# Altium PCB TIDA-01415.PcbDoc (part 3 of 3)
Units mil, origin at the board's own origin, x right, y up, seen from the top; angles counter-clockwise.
Board outline 3820.95 x 4648 mil, 4 copper layers (Top Layer, GND, PWR, Bottom Layer), stack 5.6 mil thick; 255 components, 113 nets, 599 pads, 415 vias.
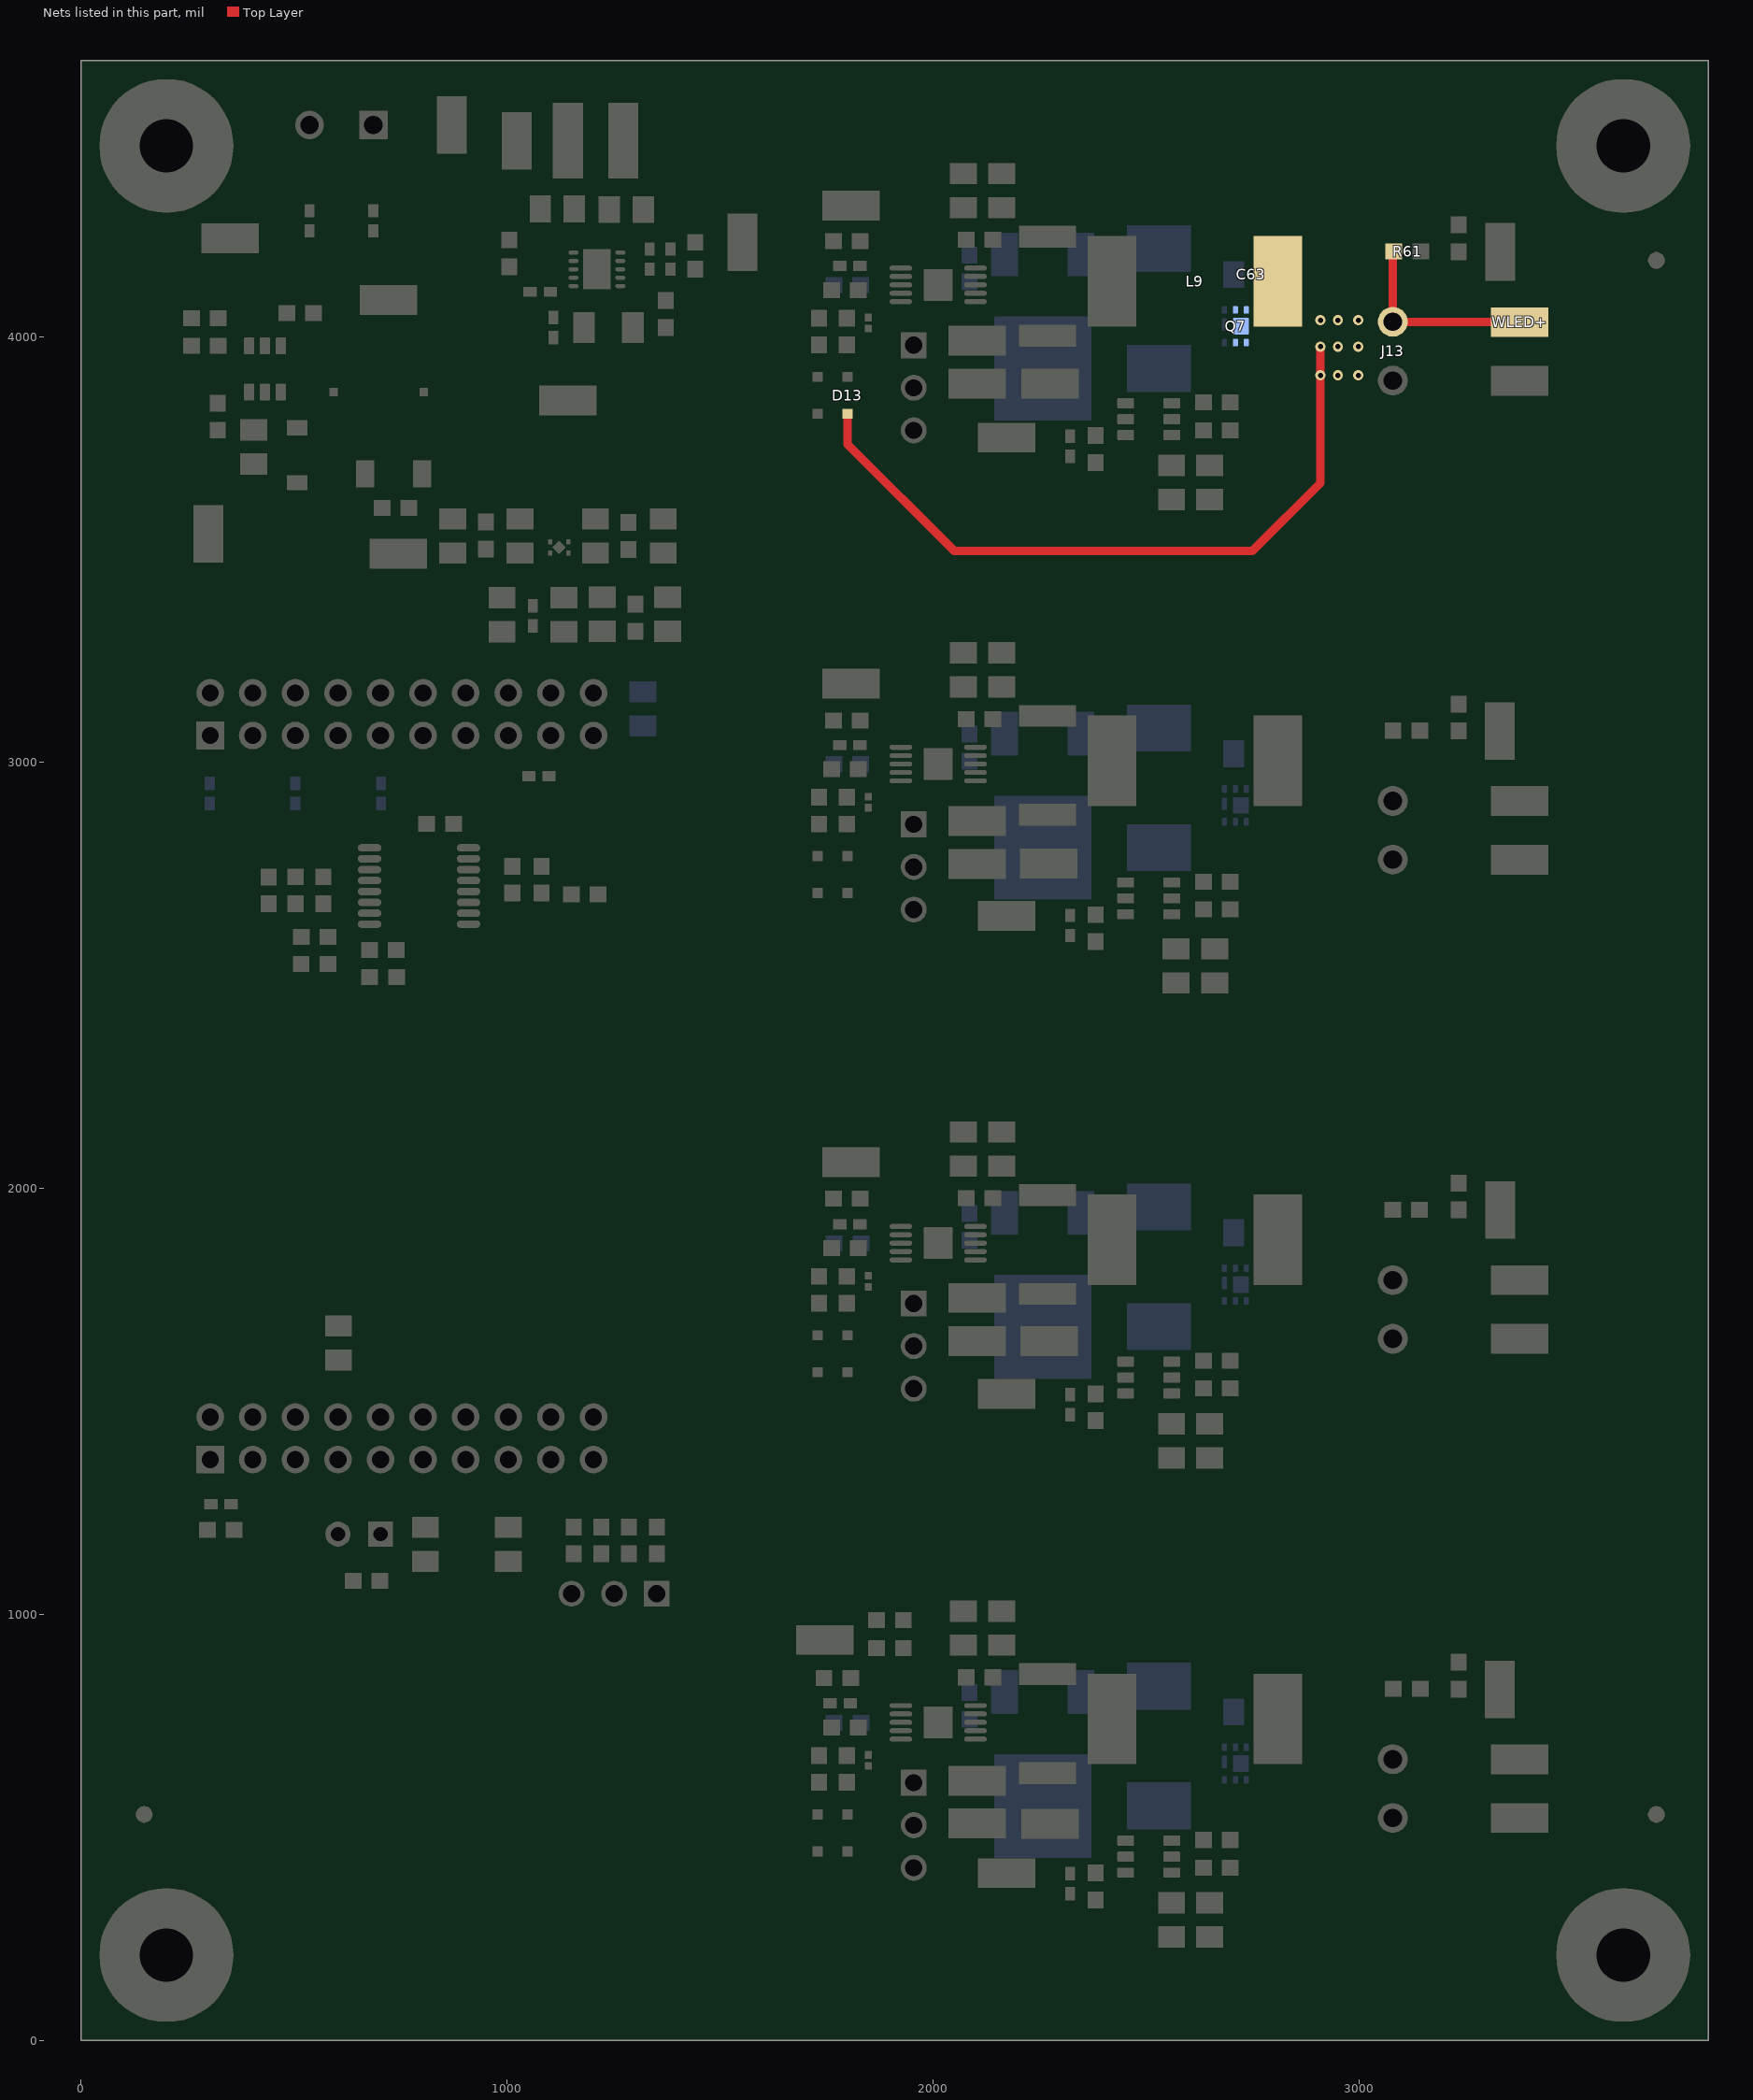
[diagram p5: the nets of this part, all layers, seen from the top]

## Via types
v1: diameter 24, hole 12, Top Layer to Bottom Layer, tented both sides, 213 vias
v2: diameter 20, hole 10, Top Layer to Bottom Layer, tented both sides, 182 vias
v3: diameter 19.68, hole 7.87, Top Layer to Bottom Layer, 20 vias

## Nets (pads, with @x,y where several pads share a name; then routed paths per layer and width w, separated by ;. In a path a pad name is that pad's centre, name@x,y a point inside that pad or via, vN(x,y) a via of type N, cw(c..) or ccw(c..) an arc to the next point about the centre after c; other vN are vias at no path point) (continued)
WLED+: C63.1 D13.2 J13.1 L9.2 Q7.1 Q7.2 Q7.5 Q7.6 Q7.8 R61.2 WLED+.1 | length 2131.3
  Top Layer w20: D13.2@1799.43,3818.69 1799.43,3747.57 2050.1,3496.9 2750,3496.9 2910,3656.9 v1(2910,3909) v1(2910,3976.53) ; R61.2@3080,4197.5 J13.1@3080,4034.8 WLED+.1@3377.2,4034.8
  other v1: 2951,3909 2999,3909 2951,3976.53 2999,3976.53 2910,4038.53 2951,4038.53 2999,4038.53
pads on no net: FID1.1 FID2.1 FID3.1 FID4.1 FID5.1 FID6.1 H1.1 H2.1 H3.1 H4.1 J5.2 J5.3 J5.5 J5.6 J5.7 J5.11 J5.12 J5.14 J5.16 J5.17 J5.19 J5.20 J10.8 J10.10 J10.13 J10.15 J10.17 J10.18 J10.19 Q1.0 Q3.0 Q5.0 Q7.0 U9.6

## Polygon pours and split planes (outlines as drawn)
GND on Top Layer "Top Layer-No Net" (solid, pour order 311): 1100,3336.92 1100,3249 1107,3242 1121,3228 1180.91,3228 1241.51,3228 1257,3243.49 1257,3336 1247,3346 1109.08,3346
GND on Top Layer "Top Layer-No Net" (solid, pour order 310): 1336,3523 1455,3523 1463,3515 1469,3509 1469,3420 1469,3387 1445,3363 1442,3360 1406,3360 1348,3360 1340,3368 1334,3374 1334,3452 1334,3520 1337,3523
+3.6V on Top Layer "Top Layer-No Net" (solid, pour order 305): 19 vertices, not listed, extent 727.5,3540 999,4040.42
+3.3V_D on Top Layer "Top Layer-No Net" (solid, pour order 309): 1276.15,3329.1 1330.46,3328.99 1340,3338.53 1343.47,3342 1366.5,3342 1428,3342 1437,3333 1437,3254 1424,3241 1392,3241 1282,3241 1272.96,3250.04 1272.96,3277.68 1272.96,3325.91
GND on Top Layer "Top Layer-No Net" (solid, pour order 308): 21 vertices, not listed, extent 840,3356.08 1020.31,3523.9
+3.3V_LP on Top Layer "Top Layer-No Net" (solid, pour order 307): 958.01,3340.01 1021.99,3340.01 1032,3330 1069,3330 1083.5,3315.5 1083.5,3295.5 1083.5,3267 1074.5,3258 1064.5,3248 1034,3248 952.96,3248 943.96,3257 941,3259.96 941,3282 941,3323
NetC30_1 on Top Layer "Top Layer-No Net" (solid, pour order 306): 32 vertices, not listed, extent 1035,3345 1325,3523.9
GND1 on Top Layer "Top Layer-No Net" (solid, remove dead copper, pour order 235): 34 vertices, not listed, extent 1893,658 2683,1125.53
GND1 on Top Layer "Top Layer-No Net" (solid, remove dead copper, pour order 237): 34 vertices, not listed, extent 1893,1783 2683,2250.53
GND1 on Top Layer "Top Layer-No Net" (solid, remove dead copper, pour order 238): 34 vertices, not listed, extent 1893,2908 2683,3375.53
GND1 on Top Layer "Top Layer-No Net" (solid, remove dead copper, pour order 239): 34 vertices, not listed, extent 1893,4033 2683,4500.53
NetQ8_3 on Top Layer "Top Layer-No Net" (solid, pour order 299): 2203,4112 2203,3977 2206,3974 2332,3974 2341,3983 2341,4122.58 2326.58,4137 2228,4137
NetQ6_3 on Top Layer "Top Layer-No Net" (solid, pour order 298): 2203,2987 2203,2852 2206,2849 2332,2849 2341,2858 2341,2997.58 2326.58,3012 2228,3012
NetQ4_3 on Top Layer "Top Layer-No Net" (solid, pour order 297): 2203,1862 2203,1727 2206,1724 2332,1724 2341,1733 2341,1872.58 2326.58,1887 2228,1887
NetD12_1 on Top Layer "Top Layer-No Net" (solid, pour order 296): 2360,4232.67 2360,3939 2373,3926 2478,3926 2488,3936 2488,4226 2477,4237 2364.33,4237
NetD9_1 on Top Layer "Top Layer-No Net" (solid, pour order 295): 2360,3107.67 2360,2814 2373,2801 2478,2801 2488,2811 2488,3101 2477,3112 2364.33,3112
NetD5_1 on Top Layer "Top Layer-No Net" (solid, pour order 294): 2360,1982.67 2360,1689 2373,1676 2478,1676 2488,1686 2488,1976 2477,1987 2364.33,1987
VIN_LED on Top Layer "Top Layer-No Net" (solid, pour order 293): 34 vertices, not listed, extent 2039,4154.53 2344,4338.53
VIN_LED on Top Layer "Top Layer-No Net" (solid, pour order 292): 34 vertices, not listed, extent 2039,3029.53 2344,3213.53
VIN_LED on Top Layer "Top Layer-No Net" (solid, pour order 291): 34 vertices, not listed, extent 2039,1904.53 2344,2088.53
NetD2_1 on Top Layer "Top Layer-No Net" (solid, pour order 249): 2360,857.67 2360,564 2373,551 2478,551 2488,561 2488,851 2477,862 2364.33,862
GND1 on Top Layer "Top Layer-No Net" (solid, pour order 273): 2381,3865.53 2497.47,3865.53 2507,3856 2507,3796 2501.53,3790.53 2455,3790.53 2417,3790.53 2398,3809.53 2370,3809.53 2366,3813.53 2365,3814.53 2365,3836.53 2365,3860.53 2369,3864.53 2370,3865.53
GND1 on Top Layer "Top Layer-No Net" (solid, pour order 272): 2381,2740.53 2497.47,2740.53 2507,2731 2507,2671 2501.53,2665.53 2455,2665.53 2417,2665.53 2398,2684.53 2370,2684.53 2366,2688.53 2365,2689.53 2365,2711.53 2365,2735.53 2369,2739.53 2370,2740.53
GND1 on Top Layer "Top Layer-No Net" (solid, pour order 271): 2381,1615.53 2497.47,1615.53 2507,1606 2507,1546 2501.53,1540.53 2455,1540.53 2417,1540.53 2398,1559.53 2370,1559.53 2366,1563.53 2365,1564.53 2365,1586.53 2365,1610.53 2369,1614.53 2370,1615.53
+10V on Top Layer "Top Layer-No Net" (solid, pour order 270): 24 vertices, not listed, extent 2523,3664.53 2767.59,3787.53
GND1 on Top Layer "Top Layer-No Net" (solid, pour order 269): 2523,3644.53 2523,3575.53 2530,3568.53 2547,3551.53 2577,3551.53 2742,3551.53 2762,3571.53 2762,3628.3 2743.77,3646.53 2742.77,3647.53 2649,3647.53 2526,3647.53
+10V on Top Layer "Top Layer-No Net" (solid, pour order 268): 24 vertices, not listed, extent 2523,2539.53 2767.59,2662.53
GND1 on Top Layer "Top Layer-No Net" (solid, pour order 267): 2523,2519.53 2523,2450.53 2530,2443.53 2547,2426.53 2577,2426.53 2742,2426.53 2762,2446.53 2762,2503.3 2743.77,2521.53 2742.77,2522.53 2649,2522.53 2526,2522.53
+10V on Top Layer "Top Layer-No Net" (solid, pour order 266): 24 vertices, not listed, extent 2523,1414.53 2767.59,1537.53
GND1 on Top Layer "Top Layer-No Net" (solid, pour order 265): 2523,1394.53 2523,1325.53 2530,1318.53 2547,1301.53 2577,1301.53 2742,1301.53 2762,1321.53 2762,1378.3 2743.77,1396.53 2742.77,1397.53 2649,1397.53 2526,1397.53
GND1 on Top Layer "Top Layer-No Net" (solid, pour order 256): 2294,361.48 2433.42,361.48 2441,353.9 2450,344.9 2450,292.53 2450,260.69 2437,247.69 2431.18,241.88 2366,241.88 2304.9,241.88 2290,256.78 2283,263.78 2283,298.9 2283,350.48 2294,361.48
NetQ2_3 on Top Layer "Top Layer-No Net" (solid, pour order 250): 2203,737 2203,602 2206,599 2332,599 2341,608 2341,747.58 2326.58,762 2228,762
GND1 on Top Layer "Top Layer-No Net" (solid, pour order 248): 2523,269.53 2523,200.53 2530,193.53 2547,176.53 2577,176.53 2766.53,176.53 2778,188 2778,264 2769.47,272.53 2649,272.53 2526,272.53
+10V on Top Layer "Top Layer-No Net" (solid, pour order 247): 24 vertices, not listed, extent 2523,289.53 2767.59,412.53
GND1 on Top Layer "Top Layer-No Net" (solid, pour order 246): 2381,490.53 2497.47,490.53 2507,481 2507,421 2501.53,415.53 2455,415.53 2417,415.53 2398,434.53 2370,434.53 2366,438.53 2365,439.53 2365,461.53 2365,485.53 2369,489.53 2370,490.53
VIN_LED on Top Layer "Top Layer-No Net" (solid, pour order 245): 34 vertices, not listed, extent 2039,779.53 2344,963.53
GND on Top Layer "Top Layer-No Net" (solid, pour order 240): 335,1276.5 335,1181.5 344,1172.5 356,1160.5 398,1160.5 413.5,1160.5 430,1177 430,1283 414.5,1298.5 384,1298.5 348,1298.5 335,1285.5 334,1284.5 334,1275.5
GND1 on Top Layer "Top Layer-No Net" (solid, pour order 233): 486,4542 486,4301 509,4278 589,4278 611,4300 611,4542 596,4557 546,4557 501,4557
GND on Top Layer "Top Layer-No Net" (solid, pour order 241): 20 vertices, not listed, extent 975,2737.5 1150,2820.5
GND on Top Layer "Top Layer-No Net" (solid, pour order 243): 496,4268 555,4268 567,4256 567,4181 558,4172 466,4172 437,4201 437,4249 437,4258 443,4264 447,4268
VIN_LED on Top Layer "Top Layer-No Net" (solid, pour order 232): 636,4542 636,4309 666,4279 735,4279 761,4305 761,4357 761,4542 746,4557 696,4557 651,4557
+3.3V_LP on Top Layer "Top Layer-No Net" (solid, pour order 234): 230,1410.5 334,1410.5 342,1402.5 343,1401.5 343,1344.5 343,1314.5 324,1295.5 323,1294.5 323,1260.5 323,1171.5 305,1153.5 217,1153.5 187,1183.5 187,1367.5
VIN_PS on Top Layer "Top Layer-No Net" (solid, pour order 244): 735,4258 742,4251 742,4226 742,4184 732,4174 634.45,4174 626,4182.45 626,4233 626,4251 633,4258
GND on Top Layer "Top Layer-No Net" (solid, pour order 276): 27 vertices, not listed, extent 230.5,3953 446.5,4126
NetC27_1 on Top Layer "Top Layer-No Net" (solid, pour order 277): 19 vertices, not listed, extent 460.5,3733 676.5,4078
VIN_PS on Top Layer "Top Layer-No Net" (solid, pour order 278): 24 vertices, not listed, extent 210.5,3711 440.31,3896
GND on Top Layer "Top Layer-No Net" (solid, pour order 279): 34 vertices, not listed, extent 354.5,3457 721.5,3727
NetC29_1 on Top Layer "Top Layer-No Net" (solid, pour order 280): 925.96,3517 925.96,3454.04 932,3448 1082,3448 1089,3455 1089,3527 1086,3530 1071.5,3530 1065.5,3524 1064.5,3524 933.5,3524 926.5,3517
GND on Top Layer "Top Layer-No Net" (solid, pour order 281): 1134.5,3617 1134.5,3536.24 1182.53,3537.03 1183.5,3538 1191.5,3538 1235.5,3538 1244.5,3547 1244.5,3628 1236.5,3636 1189.5,3636 1153.5,3636 1133.5,3616
+3.3V_A on Top Layer "Top Layer-No Net" (solid, pour order 282): 1263.5,3633.76 1263.5,3542 1265.5,3540 1267.08,3538.42 1349.5,3538.42 1414.92,3538.42 1427.5,3551 1429.5,3553 1429.5,3629 1429.5,3642 1390.5,3681 1281.5,3681 1265.5,3665 1263.5,3663 1263.5,3633
VIN_PS on Top Layer "Top Layer-No Net" (solid, pour order 283): 22 vertices, not listed, extent 945,4171 1168,4358
+10V on Top Layer "Top Layer-No Net" (solid, pour order 284): 26 vertices, not listed, extent 1226.5,4188 1495,4561
GND on Top Layer "Top Layer-No Net" (solid, pour order 285): 58 vertices, not listed, extent 998,3908.83 1353,4338
GND1 on Top Layer "Top Layer-No Net" (solid, pour order 255): 2294,1486.48 2433.42,1486.48 2441,1478.9 2450,1469.9 2450,1417.53 2450,1385.7 2437,1372.7 2431.18,1366.88 2366,1366.88 2304.9,1366.88 2290,1381.78 2283,1388.78 2283,1423.9 2283,1475.48 2294,1486.48
GND1 on Top Layer "Top Layer-No Net" (solid, pour order 254): 2294,2611.48 2433.42,2611.48 2441,2603.9 2450,2594.9 2450,2542.53 2450,2510.7 2437,2497.7 2431.18,2491.88 2366,2491.88 2304.9,2491.88 2290,2506.78 2283,2513.78 2283,2548.9 2283,2600.48 2294,2611.48
GND1 on Top Layer "Top Layer-No Net" (solid, pour order 253): 2294,3736.48 2433.42,3736.48 2441,3728.9 2450,3719.9 2450,3667.53 2450,3635.7 2437,3622.7 2431.18,3616.88 2366,3616.88 2304.9,3616.88 2290,3631.78 2283,3638.78 2283,3673.9 2283,3725.48 2294,3736.48
GND on Top Layer "Top Layer-No Net" (solid, pour order 312): 704.79,2704.66 712,2697.46 712,2670.51 701.8,2663.43 671.58,2663.43 642.5,2663.43 614.78,2654.97 608.88,2660.88 603.37,2666.38 600,2669.75 600,2696 608.66,2704.66
NetC74_1 on Top Layer "Top Layer-No Net" (solid, pour order 242): 979,2660.5 985,2654.5 1170,2654.5 1178,2662.5 1178,2695.5 1178,2706.5 1166,2718.5 1123,2718.5 990.5,2718.5 979,2707
NetC78_1 on Top Layer "Top Layer-No Net" (solid, pour order 313): 17 vertices, not listed, extent 416,2708 593,2759.98
+3.3V_D on Top Layer "Top Layer-No Net" (solid, pour order 314): 396,2693 462,2693 467,2688 468.9,2686.1 468.9,2665 468.9,2609.9 461,2602 450,2591 434,2591 407,2591 385,2613 385,2627 385,2682
+3.3V_A on Top Layer "Top Layer-No Net" (solid, pour order 315): 18 vertices, not listed, extent 1192,2636 1297,2753
WLED+ on Top Layer "Top Layer-No Net" (solid, pour order 231): 17 vertices, not listed, extent 2700.11,3829.66 3143,4266.9
BLED+ on Top Layer "Top Layer-No Net" (solid, pour order 230): 17 vertices, not listed, extent 2700.11,2704.66 3143,3141.9
GLED+ on Top Layer "Top Layer-No Net" (solid, pour order 229): 17 vertices, not listed, extent 2700.11,1579.66 3143,2016.9
RLED+ on Top Layer "Top Layer-No Net" (solid, pour order 228): 17 vertices, not listed, extent 2700.11,454.66 3143,891.9
RLED+ on Bottom Layer "Top Layer-No Net" (solid, pour order 303): 18 vertices, not listed, extent 2655,140.9 3142.04,823.9
NetQ8_3 on Bottom Layer "Top Layer-No Net" (solid, pour order 302): 20 vertices, not listed, extent 2234,4073.9 2392,4254.9
NetQ6_3 on Bottom Layer "Top Layer-No Net" (solid, pour order 301): 20 vertices, not listed, extent 2234,2948.9 2392,3129.9
NetQ4_3 on Bottom Layer "Top Layer-No Net" (solid, pour order 300): 20 vertices, not listed, extent 2234,1823.9 2392,2004.9
GND1 on Bottom Layer "Top Layer-No Net" (solid, pour order 275): 22 vertices, not listed, extent 2443,4008.9 2735,4313.9
GND1 on Bottom Layer "Top Layer-No Net" (solid, pour order 274): 22 vertices, not listed, extent 2443,2883.9 2735,3188.9
NetD12_1 on Bottom Layer "Top Layer-No Net" (solid, pour order 264): 2595,4054.9 2619,4030.9 2623,4026.9 2623,3951.9 2623,3556.9 2575,3508.9 2071.1,3508.9 2003,3577 2003,3995 2062.9,4054.9
WLED+ on Bottom Layer "Top Layer-No Net" (solid, pour order 263): 18 vertices, not listed, extent 2655,3515.9 3142,4198.9
NetD9_1 on Bottom Layer "Top Layer-No Net" (solid, pour order 262): 2595,2929.9 2619,2905.9 2623,2901.9 2623,2826.9 2623,2431.9 2575,2383.9 2021.32,2383.9 2000,2405.22 2000,2904 2025.9,2929.9
BLED+ on Bottom Layer "Top Layer-No Net" (solid, pour order 261): 18 vertices, not listed, extent 2655,2390.9 3142,3073.9
NetD5_1 on Bottom Layer "Top Layer-No Net" (solid, pour order 260): 2595,1804.9 2619,1780.9 2623,1776.9 2623,1701.9 2623,1306.9 2575,1258.9 2027.1,1258.9 2002,1284 2002,1778 2028.9,1804.9
GLED+ on Bottom Layer "Top Layer-No Net" (solid, pour order 259): 18 vertices, not listed, extent 2655,1265.9 3142.5,1948.9
GND1 on Bottom Layer "Top Layer-No Net" (solid, pour order 258): 22 vertices, not listed, extent 2443,1758.9 2735,2063.9
NetQ2_3 on Bottom Layer "Top Layer-No Net" (solid, pour order 257): 20 vertices, not listed, extent 2234,698.9 2392,879.9
GND1 on Bottom Layer "Top Layer-No Net" (solid, pour order 252): 20 vertices, not listed, extent 2420,633.9 2735,982
NetD2_1 on Bottom Layer "Top Layer-No Net" (solid, pour order 251): 2595,679.9 2619,655.9 2623,651.9 2623,576.9 2623,181.9 2575,133.9 2037.1,133.9 2003.48,167.52 2003.48,642.48 2040.9,679.9
VIN_PS on Bottom Layer "Top Layer-No Net" (solid, pour order 286): 603,4407 1000,4407 1055,4352 1066,4341 1066,4072 1066,4027 827,3788 727,3688 334,3688 218,3688 163,3743 163,4039 430,4306 533,4409 603,4409
GND on PWR "Top Layer-No Net" (solid, remove dead copper, pour order 316): 0,4648 3820,4648 3820.95,4647.05 3820.95,0 0,0 0,4648
+3.3V_A on PWR "Top Layer-No Net" (solid, pour order 289): 23 vertices, not listed, extent 461,994 1538,3804.69
+10V on PWR "Top Layer-No Net" (solid, pour order 287): 1361,4540 1361,4341.85 1382.85,4320 1528,4320 1636,4428 2005,4428 2353,4428 2607,4174 2607,166 2635,138 2769,138 2786,155 2786,4263 2472,4577 1398,4577
VIN_LED on PWR "Top Layer-No Net" (solid, pour order 288): 28 vertices, not listed, extent 624,316 2416,4572
+3.3V_D on PWR "Top Layer-No Net" (solid, pour order 290): 19 vertices, not listed, extent 205,1803 1434,3668
GND1 on GND "Bottom Layer-No Net 1" (solid, pour order 236): 68 vertices, not listed, extent 472,229.79 3316,4558
GND on GND "Top Layer-No Net" (solid, remove dead copper, pour order 304): 0,4648 3820.95,4648 3820.95,0 0,0 0,4648

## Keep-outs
Keep-Out Layer:
  the board outline again, w6
  text ".Layer_Name" at 577,-805.49 h60

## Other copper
Top Layer:
  text ".Layer_Name" at 577,-805.49 h60
GND:
  text ".layer_Name" at 714,-801 h60
PWR:
  text ".layer_Name" at 718,-797 h60
Bottom Layer:
  text ".Layer_Name" at 577,-805.49 h60

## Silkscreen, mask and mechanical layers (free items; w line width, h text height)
Top Overlay:
  circle w6: c490,4014 r5.83
  circle w6: c3243,663 r5.66
  circle w6: c3243,1787 r5.66
  circle w6: c3247,2906 r5.66
  circle w6: c3251,4032 r5.66
  circle w6: c1143.67,3464 r3.61
  circle w6: c1125,4214 r4.47
  region: 744.21,572.35 444.21,572.35 444.21,472.35 744.21,472.35
  lines w6: 616.33,2468.02 616.33,2471.36 629,2484.03 629,2545.4 639.6,2556 ; 1355.5,4230 1355.5,4240.5 1389.56,4274.56 1409,4274.56 ; 1620,691 1635,706 1696.67,706 1705.69,696.98 ; 1620,1816 1635,1831 1696.67,1831 1705.69,1821.98 ; 1620,2941 1635,2956 1696.67,2956 1705.69,2946.98 ; 1620,4066 1635,4081 1696.67,4081 1705.69,4071.98 ; 2015,305 2015,574.94 2020.06,580 ; 2015,1430 2015,1706 2024,1715 ; 2015,2558 2015,2834 2026,2845 ; 2015,3687 2015,3959 2024,3968 ; 928.58,3258.63 942.21,3245 1451.47,3245 1570.47,3364 1980,3364 2004,3388 2004,3554 1973,3585 1615,3585 1471,3441 1159.58,3441 970.11,3441 951.58,3441 942.58,3441 928.58,3427 928.58,3258.63
  text "1" at 1885,3959 h35
  text "2" at 1871,3853 h35
  text "3" at 1871,3766 h35
  text "1" at 1885,2834 h35
  text "2" at 1871,2728 h35
  text "3" at 1871,2641 h35
  text "1" at 1885,1709 h35
  text "2" at 1870,1595 h35
  text "3" at 1871,1516 h35
  text "1" at 1885,584 h35
  text ".PRJ_Number" at 805.21,502.35 h35
  text ".PCB_Rev" at 1196.21,500.75 h35
  text "-" at 1153.69,499.35 h35
  text "2" at 1871,478 h35
  text "3" at 1871,391 h35
  text ".Layer_Name" at 577,-805.49 h60
Bottom Overlay:
  text ".Layer_Name" at 577,-805.49 h60
Top Paste:
  text ".Layer_Name" at 577,-805.49 h60
Bottom Paste:
  text ".Layer_Name" at 577,-805.49 h60
Top Solder:
  text ".Layer_Name" at 577,-805.49 h60
  text ".Layer_Name" at 577,-805.49 h60
Bottom Solder:
  text ".Layer_Name" at 577,-805.49 h60
Drill Guide:
  text ".Layer_Name" at 577,-805.49 h60
M1 Board Outline:
  the board outline again, w10
M2 Board Dimensions:
  rectangle: 125,-347 500,-222
  rectangle: 0,-222 125,-97
  lines w7: 0,-222 1000,-222 ; 125,-347 125,-97 ; 250,-347 250,-97 ; 500,-347 500,-97 ; 750,-347 750,-97 ; 0,-347 0,-97 1000,-97 1000,-347 0,-347
M3 3D STEP Top:
  text ".Layer_Name" at 577,-805.49 h60
M4 3D STEP Bottom:
  text ".Layer_Name" at 577,-805.49 h60
M5 Assembly Top:
  circle w6: c1142,3668 r7.62
  circle w6: c3324,4025 r7.62
  circle w6: c3323,2921 r7.62
  circle w6: c3327,1788 r7.62
  circle w6: c3326,672 r7.62
  circle w6: c707.65,1185 r6.4
  lines w10: -292,-877.17 6308,-877.17 ; -292,-673.83 6310,-673.83 ; -292,-470.5 -292,-1080.5 3713,-1080.5 6310,-1080.5 6310,-470.5 -291.5,-470.5 -291.5,-1080.5 1284,-1080.5 ; 2173,-1080.5 2173,-470.5 ; 3440,-673.83 3440,-470.5 ; 4280,-673.83 4280,-470.5 ; 4902,-1087 4902,-884.17
  text "COMPONENTS MARKED 'DNP' SHOULD NOT BE POPULATED." at 1153.5,-265.5 h30
  text "ASSEMBLY VARIANT:" at 1153,-381 h30
  text ".VariantName" at 2189,-381 h30
  text "PCB VIEWED FROM TOP SIDE" at -228.5,-602.67 h30
  text "BOARD #:" at 2248,-602.67 h30
  text ".PRJ_Number" at 2793.5,-602.67 h30
  text "REV:" at 3638,-602.67 h30
  text ".PCB_Rev" at 3929.5,-602.67 h30
  text "SVN REV:" at 4476,-602.67 h30
  text ".VersionControl_RevNumber" at 4982,-602.67 h30
  text "TID #:" at 2248,-806 h30
  text ".TID" at 2793.5,-806 h30
  text ".layer_Name" at 592,-810 h60
  text "PLOT NAME =" at -228.5,-1011.34 h30
  text ".plot_File_Name" at 577,-1011.34 h30
  text "GENERATED    :" at 2250,-1011.34 h30
  text ".Print_Date" at 3119.5,-1011.34 h30
  text ".Print_Time" at 3848.5,-1011.34 h30
  text "TEXAS INSTRUMENTS" at 5113,-1011.34 h30
M6 Assembly Bottom:
  circle w6: c2204,4169 r7.62
  circle w6: c2202,3042 r7.62
  circle w6: c2200,1921 r7.62
  circle w6: c2205,803 r7.62
  lines w10: -292.5,-674.33 6309.5,-674.33 ; -290.5,-877.67 6309.5,-877.67 ; 1115.5,-1087.5 1115.5,-884.67 ; 1737.5,-674.33 1737.5,-471 ; 2577.5,-674.33 2577.5,-471 ; 3844.5,-1081 3844.5,-471 ; 4733.5,-1081 6309,-1081 6309,-471 -292.5,-471 -292.5,-1081 2304.5,-1081 6309.5,-1081 6309.5,-471
  text "COMPONENTS MARKED 'DNP' SHOULD NOT BE POPULATED." at 6102,-265 h30
  text ".VariantName" at 5058,-381 h30
  text "ASSEMBLY VARIANT:" at 6097,-381 h30
  text ".VersionControl_RevNumber" at 1035.5,-603.17 h30
  text "SVN REV:" at 1541.5,-603.17 h30
  text ".PCB_Rev" at 2088,-603.17 h30
  text "REV:" at 2379.5,-603.17 h30
  text ".PRJ_Number" at 3224,-603.17 h30
  text "BOARD #:" at 3769.5,-603.17 h30
  text "PCB VIEWED FROM BOTTOM SIDE" at 6246,-603.17 h30
  text ".layer_Name" at 5558,-793 h60
  text ".TID" at 3224,-806.5 h30
  text "TID #:" at 3769.5,-806.5 h30
  text "TEXAS INSTRUMENTS" at 904.5,-1011.84 h30
  text ".Print_Time" at 2169,-1011.84 h30
  text ".Print_Date" at 2898,-1011.84 h30
  text "GENERATED    :" at 3767.5,-1011.84 h30
  text ".plot_File_Name" at 5440.5,-1011.84 h30
  text "PLOT NAME =" at 6246,-1011.84 h30
M9 Title Sheet:
  drawing of 57 lines, arcs and shapes, not listed
  text "1" at 739.84,8089.5 h70
  text "2" at 3235.5,8089.5 h70
  text "3" at 5724.84,8089.5 h70
  text "4" at 8231.51,8089.5 h70
  text "5" at 10730.5,8089.5 h70
  text "6" at 13235.5,8089.5 h70
  text "A" at -416.5,6946.5 h70
  text "A" at 14383.5,6946.5 h70
  text "B" at -416.5,4566.5 h70
  text "B" at 14383.5,4566.5 h70
  text "C" at -416.5,2191.5 h70
  text "C" at 14383.5,2191.5 h70
  text "PROJECT TITLE:" at 11343.5,330.5 h45
  text ".PRJ_Title" at 11393.5,197.17 h35
  text "DESIGNED FOR:" at 11343.5,29.5 h45
  text ".PRJ_Customer" at 11393.5,-110.5 h70
  text "D" at -416.5,-178.5 h70
  text "D" at 14383.5,-178.5 h70
  text "FILE NAME:" at 11343.5,-270.5 h45
  text ".PCB_File_Name_No_Path" at 11393.5,-390.5 h70
  text "Texas Instruments (TI) and/or its licensors do not warrant the accuracy or completeness of this specification" at 6374,-552.34 h45
  text "ENGINEER:" at 11343.5,-560.5 h45
  text "LAYOUT BY:" at 12848.5,-560.5 h45
  text "or any information contained therein. TI and/or its licensors do not warrant that this design will meet" at 6329.01,-665 h45
  text ".PRJ_Engineer" at 11393.5,-715.49 h70
  text ".PCB_Layout" at 12899,-715.49 h70
  text "the specifications, will be suitable for your application or fit for any particular purpose, or will operate in" at 6329.01,-777.67 h45
  text "ALTIUM DESIGNER VERSION:" at 12848.5,-870.5 h45
  text "an implementation. TI and/or its licensors do not warrant that the design is production worthy. You should" at 6329.01,-890.33 h45
  text "completely validate and test your design implementation to confirm the system functionality for your application." at 6374,-1003 h45
  text ".print_Scale" at 11393.5,-1003.83 h70
  text ".Application_BuildNumber" at 12899,-1003.83 h70
  text "1" at 739.84,-1210.5 h70
  text "2" at 3235.5,-1210.5 h70
  text "3" at 5724.84,-1210.5 h70
  text "4" at 8231.51,-1210.5 h70
  text "5" at 10730.5,-1210.5 h70
  text "6" at 13235.5,-1210.5 h70
M10 Fab Notes:
  drawing of 173 lines, arcs and shapes, not listed
  text "DESIGN INFORMATION" at 12378.02,6254 h60
  text "MIN. TRACK WIDTH:" at 11733.46,6074 h60
  text "8" at 12829.7,6074 h60
  text "MIL" at 12984.46,6074 h60
  text "MIN. CLEARANCE:" at 11733.46,5942 h60
  text "4.7" at 12769.7,5942 h60
  text "Mil" at 12984.46,5942 h60
  text "MIN. VIA PAD SIZE:" at 11733.46,5810 h60
  text "19.685" at 12618,5810 h60
  text "MIL" at 12984.46,5810 h60
  text "5 Mil" at 12561,5670 h60
  text "MINIMUM ANNULAR RING" at 11404.23,5664 h60
  text "EXTERNAL" at 13136.46,5664 h60
  text "PER" at 11604.23,5546 h60
  text "IPC-D-275 CLASS 2 LEVEL C" at 11824.23,5546 h60
  text "MIL, HOLES" at 13312.46,5433.71 h60
  text "+/-" at 12920,5433 h60
  text "+/-" at 13774,5433 h60
  text "REGISTRATION TOLERANCES:" at 11404.23,5428 h60
  text "METAL" at 12604,5428 h60
  text "5" at 13180.2,5428 h60
  text "3" at 14013.2,5428 h60
  text "MIL" at 14129.46,5428 h60
  text "+/-" at 13774,5315 h60
  text "HOLE SIZE TOLERANCE (UNLESS OTHERWISE SPECIFIED):" at 11404.23,5310 h60
  text "3" at 14013.2,5310 h60
  text "MIL" at 14129.46,5310 h60
  text "MATERIAL:" at 11329.46,5100.54 h60
  text "FR-4 High Tg" at 12315.9,4960.21 h60
  text "FR-408" at 11750.46,4951.64 h60
  text "OTHER" at 13238.46,4951.64 h60
  text "X" at 12161,4948 h60
  text "63 MIL (1.6mm) +/-10%" at 12070.56,4788.92 h60
  text "THICKNESS:" at 11404.23,4784.64 h60
  text "X" at 11942.4,4784.64 h60
  text "OTHER" at 13355.46,4784.64 h60
  text "TOLERANCE:" at 11404.23,4626.64 h60
  text "X" at 12243.53,4626.64 h60
  text "ANSI IPC-6012 TYPE 3 CLASS 2" at 12430.48,4626.64 h60
  text "OTHER +/-" at 12430.46,4470.64 h60
  text "BOW & TWIST:" at 11404.23,4313.64 h60
  text "X" at 12243.53,4313.64 h60
  text "ANSI IPC-6012 TYPE 3 CLASS 2" at 12430.48,4313.64 h60
  text "OTHER +/-" at 12430.46,4155.13 h60
  text "DRILLING:" at 11329.46,4016.64 h60
  text "REFERENCE:" at 11404.23,3899.64 h60
  text "X" at 12052.46,3899.64 h60
  text "AS SHOWN" at 12239.46,3899.64 h60
  text "X" at 12953.46,3899.64 h60
  text "NC_DRILL FILES" at 13090.46,3899.64 h60
  text "PTH COPPER THICKNESS:" at 11404.23,3741.64 h60
  text "X" at 12534.46,3741.64 h60
  text "20-30 um" at 12671.46,3741.64 h60
  text "OTHER" at 13388.46,3741.64 h60
  text "BOARD FINISH:" at 11329.46,3582.64 h60
  text "SILKSCREEN:" at 11484.68,3464.64 h60
  text "X" at 12433.46,3464.64 h60
  text "TOP" at 12559.46,3464.64 h60
  text "X" at 12943.46,3464.64 h60
  text "BOTTOM" at 13070.46,3464.64 h60
  text "SILKSCREEN COLOR:" at 11484.68,3297.64 h60
  text "X" at 12432.42,3297.64 h60
  text "WHITE" at 12559.46,3297.64 h60
  text "OTHER" at 13070.46,3297.64 h60
  text "X" at 12563.42,3138.44 h60
  text "GREEN" at 12690.46,3138.44 h60
  text "OTHER" at 13308.46,3138.44 h60
  text "SOLDER RESIST COLOR:" at 11484.68,3127.64 h60
  text "X" at 12563.42,2968.44 h60
  text "MATTE" at 12690.46,2968.44 h60
  text "SEMI-GLOSS" at 13308,2967.8 h60
  text "IMMERSION GOLD (ENIG)" at 12390.46,2779.92 h60
  text "ENEPIG" at 13728,2776.64 h60
  text "SURFACE FINISH:" at 11329.46,2775.64 h60
  text "X" at 12203.51,2775.64 h60
  text "IMM. TIN/SILVER OR EQUIV" at 11659,2618.64 h60
  text "OTHER" at 13090.46,2618.64 h60
  text "ARRAY/PANEL:" at 11329.46,2439.64 h60
  text "CUT AND TRIM PER M1 BOARD OUTLINE" at 12390.46,2435.35 h60
  text "N.C. ROUTE" at 12390.46,2283.64 h60
  text "X" at 13069.46,2283.64 h60
  text "V. SCORE" at 13256.46,2283.64 h60
  text "CERTIFICATION:" at 11329.46,2146.64 h60
  text "MATERIALS AND WORKMANSHIP FOR ALL PCBS" at 12054.46,2146.64 h60
  text "TO MEET OR EXCEED THE REQUIREMENTS OF:" at 12054.46,2048.64 h60
  text "X" at 11680.96,1912.13 h60
  text "ANSI IPC-A-600F CLASS ->" at 11819.96,1912.13 h60
  text "X" at 13459.02,1912.13 h60
  text "2" at 13577.96,1912.14 h60
  text "1" at 13262.96,1910.64 h60
  text "3" at 13931.96,1910.64 h60
  text "X" at 12495.02,1752.64 h60
  text "RoHS" at 12631.96,1752.64 h60
  text "OTHER" at 13276.36,1752.64 h60
  text "PER ORDER" at 13673.42,1752.64 h60
  text "ALL BOARDS MUST MEET OR EXCEED UL94-V0 REQUIREMENTS." at 11357,1587 h60
  text "PCB MUST BEAR THE UL94V-0 UL REGISTERED MATERIAL ID NUMBER" at 11357,1467 h60
  text "ADDITIONAL REQUIREMENTS:" at 11329.46,1293.64 h60
  text "MICROSECTION:" at 11404.23,1178.64 h60
  text "YES" at 12309.96,1178.64 h60
  text "REQUIRED" at 13171.46,1022.49 h60
  text "BARE BOARD ELEC. TEST:" at 11404.23,1019.64 h60
  text "NONE" at 12709.96,1019.64 h60
  text "X" at 13044.46,1019.64 h60
  text "PER ORDER" at 13763.46,1019.64 h60
M11 Gerber Information:
  lines w10: -292,-877.17 6308,-877.17 ; -292,-673.83 6310,-673.83 ; -292,-470.5 -292,-1080.5 3713,-1080.5 6310,-1080.5 6310,-470.5 -291.5,-470.5 -291.5,-1080.5 1284,-1080.5 ; 2173,-1080.5 2173,-470.5 ; 3440,-673.83 3440,-470.5 ; 4280,-673.83 4280,-470.5 ; 4902,-1087 4902,-884.17
  text "ALL ARTWORK VIEWED FROM TOP SIDE" at -228.5,-602.67 h60
  text "BOARD #:" at 2248,-602.67 h60
  text ".PRJ_Number" at 2793.5,-602.67 h60
  text "REV:" at 3638,-602.67 h60
  text ".PCB_Rev" at 3929.5,-602.67 h60
  text "SVN REV:" at 4476,-602.67 h60
  text ".VersionControl_RevNumber" at 4982,-602.67 h60
  text "LAYER NAME =" at -228.5,-805.49 h60
  text "TID #:" at 2248,-806 h60
  text ".TID" at 2793.5,-806 h60
  text "PLOT NAME =" at -228.5,-1011.34 h60
  text ".plot_File_Name" at 577,-1011.34 h60
  text "GENERATED    :" at 2250,-1011.34 h60
  text ".Print_Date" at 3119.5,-1011.34 h60
  text ".Print_Time" at 3848.5,-1011.34 h60
  text "TEXAS INSTRUMENTS" at 5113,-1011.34 h60
M12 Stackup:
  drawing of 295 lines, arcs and shapes, not listed
  text "Layer" at 9727.5,7792.5 h60
  text "Name" at 10137.41,7792.5 h60
  text "Material" at 11067.16,7792.5 h60
  text "Thickness" at 11926.92,7792.5 h60
  text "Constant" at 12576.76,7792.5 h60
  text "Board Layer Stack" at 13146.62,7792.5 h60
  text "1" at 9727.5,7672.5 h60
  text "Top Overlay" at 10137.41,7672.5 h60
  text "2" at 9727.5,7552.5 h60
  text "Top Solder" at 10137.41,7552.5 h60
  text "Solder Resist" at 11067.16,7552.5 h60
  text "0.40mil" at 11926.92,7552.5 h60
  text "3.5" at 12576.76,7552.5 h60
  text "3" at 9727.5,7432.5 h60
  text "Top Layer" at 10137.41,7432.5 h60
  text "Copper" at 11067.16,7432.5 h60
  text "1.40mil" at 11926.92,7432.5 h60
  text "4" at 9727.5,7312.5 h60
  text "Dielectric1" at 10137.41,7312.5 h60
  text "FR-4 High Tg" at 11067.16,7312.5 h60
  text "4.2" at 12576.76,7312.5 h60
  text "5" at 9727.5,7192.5 h60
  text "GND" at 10137.41,7192.5 h60
  text "Copper" at 11067.16,7192.5 h60
  text "1.40mil" at 11926.92,7192.5 h60
  text "6" at 9727.5,7072.5 h60
  text "Dielectric2" at 10137.41,7072.5 h60
  text "FR-4 High Tg" at 11067.16,7072.5 h60
  text "4.2" at 12576.76,7072.5 h60
  text "7" at 9727.5,6952.5 h60
  text "PWR" at 10137.41,6952.5 h60
  text "Copper" at 11067.16,6952.5 h60
  text "1.40mil" at 11926.92,6952.5 h60
  text "8" at 9727.5,6832.5 h60
  text "Dielectric3" at 10137.41,6832.5 h60
  text "FR-4 High Tg" at 11067.16,6832.5 h60
  text "4.2" at 12576.76,6832.5 h60
  text "9" at 9727.5,6712.5 h60
  text "Bottom Layer" at 10137.41,6712.5 h60
  text "Copper" at 11067.16,6712.5 h60
  text "1.40mil" at 11926.92,6712.5 h60
  text "10" at 9727.5,6592.5 h60
  text "Bottom Solder" at 10137.41,6592.5 h60
  text "Solder Resist" at 11067.16,6592.5 h60
  text "0.40mil" at 11926.92,6592.5 h60
  text "3.5" at 12576.76,6592.5 h60
  text "11" at 9727.5,6472.5 h60
  text "Bottom Overlay" at 10137.41,6472.5 h60
M13 Component Bodies Top:
  text ".Layer_Name" at 577,-805.49 h60
M14 Component Bodies Bottom:
  text ".Layer_Name" at 577,-805.49 h60
M15 Courtyards Top:
  text ".Layer_Name" at 577,-805.49 h60
M16 Courtyards Bottom:
  text ".Layer_Name" at 577,-805.49 h60
Drill Drawing:
  circle w10: c5039.62,3351.83 r33.33
  lines w10: 5006.29,3485.17 5022.96,3485.17 5039.62,3468.5 5056.29,3485.17 5072.96,3485.17 5056.29,3501.83 5072.96,3518.5 5056.29,3518.5 5039.62,3535.17 5022.96,3518.5 5006.29,3518.5 5022.96,3501.83 5006.29,3485.17 ; 5006.29,3685.17 5072.96,3685.17 5039.62,3618.5 5006.29,3685.17 ; 5006.29,3768.5 5039.62,3785.17 5072.96,3768.5 5056.29,3801.83 5072.96,3835.17 5039.62,3818.5 5006.29,3835.17 5022.96,3801.83 5006.29,3768.5 ; 5006.29,3918.5 5072.96,3918.5 5072.96,3985.17 5006.29,3985.17 5006.29,3918.5 ; 5006.29,4101.83 5039.62,4068.5 5072.96,4101.83 5039.62,4135.17 5006.29,4101.83 ; 5006.29,4218.5 5006.29,4235.17 5022.96,4251.83 5006.29,4268.5 5006.29,4285.17 5022.96,4285.17 5039.62,4268.5 5056.29,4285.17 5072.96,4285.17 5072.96,4268.5 5056.29,4251.83 5072.96,4235.17 5072.96,4218.5 5056.29,4218.5 5039.62,4235.17 5022.96,4218.5 5006.29,4218.5 ; 5006.29,4385.17 5022.96,4385.17 5022.96,4368.5 5056.29,4368.5 5056.29,4385.17 5072.96,4385.17 5072.96,4418.5 5056.29,4418.5 5056.29,4435.17 5022.96,4435.17 5022.96,4418.5 5006.29,4418.5 5006.29,4385.17
  lines w15: 4946.5,3273.5 8825.47,3273.5 ; 4946.5,4473.5 8825.47,4473.5 ; 5497.38,3123.5 5497.38,4623.5 ; 6195.19,3123.5 6195.19,4623.5 ; 7540.79,3123.5 7540.79,4623.5 ; 8046.67,3123.5 8046.67,4623.5 ; 4946.5,3123.5 8825.47,3123.5 8825.47,4623.5 4946.5,4623.5 4946.5,3123.5
  text "Symbol" at 5036.5,4518.5 h72
  text "Hit Count" at 5542.38,4518.5 h72
  text "Finished Hole Size" at 6240.19,4518.5 h72
  text "Plated" at 7585.79,4518.5 h72
  text "Hole Type" at 8091.67,4518.5 h72
  text "20" at 5542.38,4368.5 h60
  text "7.87mil (0.200mm)" at 6240.19,4368.5 h60
  text "PTH" at 7585.79,4368.5 h60
  text "Round" at 8091.67,4368.5 h60
  text "182" at 5542.38,4218.5 h60
  text "10.00mil (0.254mm)" at 6240.19,4218.5 h60
  text "PTH" at 7585.79,4218.5 h60
  text "Round" at 8091.67,4218.5 h60
  text "213" at 5542.38,4068.5 h60
  text "12.00mil (0.305mm)" at 6240.19,4068.5 h60
  text "PTH" at 7585.79,4068.5 h60
  text "Round" at 8091.67,4068.5 h60
  text "2" at 5542.38,3918.5 h60
  text "33.46mil (0.850mm)" at 6240.19,3918.5 h60
  text "PTH" at 7585.79,3918.5 h60
  text "Round" at 8091.67,3918.5 h60
  text "40" at 5542.38,3768.5 h60
  text "40.00mil (1.016mm)" at 6240.19,3768.5 h60
  text "PTH" at 7585.79,3768.5 h60
  text "Round" at 8091.67,3768.5 h60
  text "15" at 5542.38,3618.5 h60
  text "40.16mil (1.020mm)" at 6240.19,3618.5 h60
  text "PTH" at 7585.79,3618.5 h60
  text "Round" at 8091.67,3618.5 h60
  text "10" at 5542.38,3468.5 h60
  text "43.31mil (1.100mm)" at 6240.19,3468.5 h60
  text "PTH" at 7585.79,3468.5 h60
  text "Round" at 8091.67,3468.5 h60
  text "4" at 5542.38,3318.5 h60
  text "125.98mil (3.200mm)" at 6240.19,3318.5 h60
  text "PTH" at 7585.79,3318.5 h60
  text "Round" at 8091.67,3318.5 h60
  text "486 Total" at 5542.38,3168.5 h60
  text "DRILL TOLERANCE" at 5004,2811.6 h60
  text "FOR PTH +/- 3MIL" at 5001,2656 h60
  text "12mil drill:+0/-12mil" at 4995,2548 h60
  text "10mil drill:+0/-10mil" at 4992,2423.58 h60
  text "7.87mil drill:+0/-7.87mil" at 4999,2295.49 h60
  text "This is not an impedance controlled board" at 4983,2167.11 h60
  text "All vias are tented except the vias on thermal pad" at 4993,1996 h60
  text ".Layer_Name" at 577,-805.49 h60
M17 Embedded Cavity:
  text ".Layer_Name" at 577,-805.49 h60
M18 Embedded Assembly:
  text ".Layer_Name" at 577,-805.49 h60
M19 Embedded Keepout:
  text ".Layer_Name" at 577,-805.49 h60

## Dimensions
0,0 to 3820.95,0 on M2 Board Dimensions
0,0 to 0,4648 on M2 Board Dimensions
0,-347 to 1000,-347 on M2 Board Dimensions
